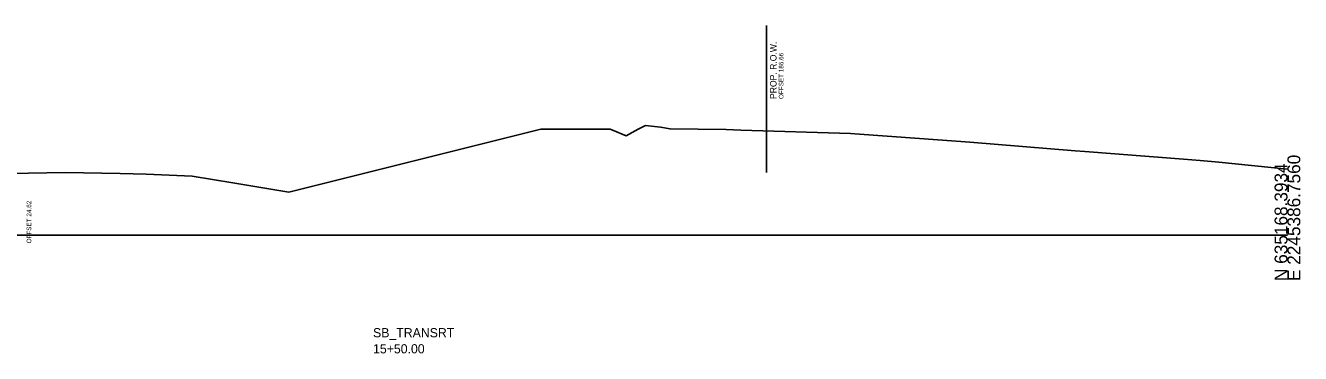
# Model space of a CAD drawing. Extents: x -26 to 669, y -22 to 6560.
# Drawn here: x 325.4 to 602.8, y 5474.2 to 5545.6 of the extents above; entities that cross this region are included whole.
import ezdxf

# ---------------------------------------------------------------- set-up
doc = ezdxf.new("R2010")
doc.units = 0
for name, color, linetype in [('DESIGN - ROW - Right-of-Way and Easement Labels', 7, 'Continuous'), ('DESIGN - ROW - Right-of-Way Linework', 7, 'Continuous'), ('DESIGN - SHEET - Light Grid', 7, 'Continuous'), ('DESIGN - TYPICAL - Subgrade Tie Text', 7, 'Continuous'), ('DESIGN - TYPICAL - Warning Text', 7, 'Continuous'), ('SURVEY - GROUND - Top of Ground', 7, 'Continuous')]:
    doc.layers.add(name, color=color, linetype=linetype)

msp = doc.modelspace()

# ---------------------------------------------------------------- linework, layer by layer
at = {"layer": 'DESIGN - ROW - Right-of-Way Linework'}
msp.add_line((486.66, 5513.62), (486.66, 5545.62), dxfattribs=at)
at = {"layer": 'DESIGN - SHEET - Light Grid'}
msp.add_line((300, 5500), (600, 5500), dxfattribs=at)
at = {"layer": 'SURVEY - GROUND - Top of Ground'}
for p, q in [((382.64, 5509.36), (437.54, 5523.08)), ((322, 5513.37), (334, 5513.61)), ((334, 5513.61), (346, 5513.37)), ((346, 5513.37), (351.64, 5513.26)), ((351.64, 5513.26), (361.64, 5512.86)), ((361.64, 5512.86), (370.51, 5511.38)), ((370.51, 5511.38), (382.64, 5509.36))]:
    msp.add_line(p, q, dxfattribs=at)
msp.add_lwpolyline([(437.54, 5523.08), (450.38, 5523.07), (451.63, 5523.07), (452.62, 5523.07), (453, 5522.91), (456.11, 5521.59), (458.71, 5523.04), (460.27, 5523.82), (463.56, 5523.49), (465.64, 5523.11), (477.83, 5522.96), (481.01, 5522.87), (504.92, 5522.09), (505.86, 5522.06), (519.93, 5521.03), (530.91, 5520.23), (553.78, 5518.36), (555.9, 5518.18), (577.39, 5516.52), (580.99, 5516.23), (585.08, 5515.88), (600, 5514.36)], dxfattribs=at)

# ---------------------------------------------------------------- texts
at = {"layer": 'DESIGN - ROW - Right-of-Way and Easement Labels'}
for s, height, p in [('PROP. R.O.W.', 1.4, (488.81, 5529.62)), ('OFFSET 186.66', 1, (490.31, 5529.62))]:
    msp.add_text(s, height=height, rotation=90, dxfattribs=at).set_placement(p)
at = {"layer": 'DESIGN - SHEET - Light Grid'}
for s, p in [('E 2245386.7560', (602.8, 5490)), ('N 635168.3934', (600, 5490))]:
    msp.add_text(s, height=2.8, rotation=90, dxfattribs=at).set_placement(p)
at = {"layer": 'DESIGN - TYPICAL - Subgrade Tie Text'}
msp.add_text('OFFSET 24.62', height=1, rotation=90, dxfattribs=at).set_placement((326.62, 5498.19))
at = {"layer": 'DESIGN - TYPICAL - Warning Text'}
for s, p in [('SB_TRANSRT', (401, 5477.75)), ('SB_TRANSRT', (401, 5477.75)), ('SB_TRANSRT', (401, 5477.75)), ('15+50.00', (401, 5474.25)), ('15+50.00', (401, 5474.25)), ('15+50.00', (401, 5474.25))]:
    msp.add_text(s, height=2, dxfattribs=at).set_placement(p)

doc.saveas('drawing.dxf')
